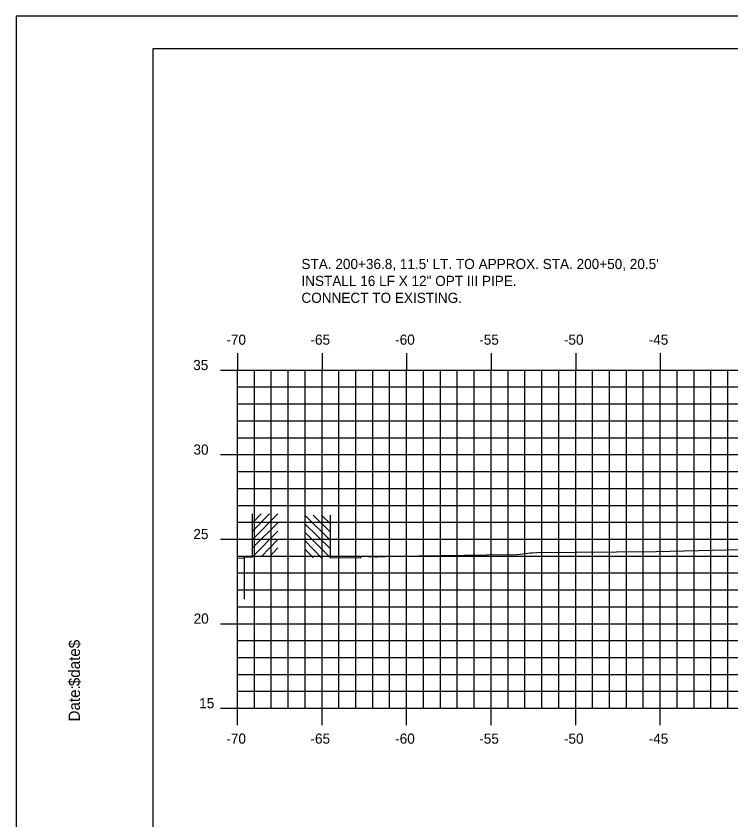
# Model space of a CAD drawing. Extents: x 1023237 to 1023407, y 394697 to 394807.
# Drawn here: x 1023236.57 to 1023278.84, y 394759 to 394806.55 of the extents above; entities that cross this region are included whole.
import ezdxf

# ---------------------------------------------------------------- set-up
doc = ezdxf.new("R2010")
doc.units = 0
for name, color, linetype in [('BORDER', 7, 'Continuous'), ('D_Drainage_Text', 7, 'Continuous'), ('H_V ANNOTATION', 7, 'Continuous'), ('MAJOR', 7, 'Continuous'), ('MINOR', 7, 'Continuous'), ('PLOT BOUNDARY', 7, 'Continuous'), ('S_Buildings_SillElevation', 7, 'Continuous'), ('S_Roadway_Centerline', 7, 'Continuous'), ('S_Roadway_Edge_Pavement', 7, 'Continuous')]:
    doc.layers.add(name, color=color, linetype=linetype)

msp = doc.modelspace()

# ---------------------------------------------------------------- linework, layer by layer
at = {"layer": 'BORDER'}
for p, q in [((1023404.664, 394804.607), (1023244.664, 394804.607)), ((1023244.664, 394804.607), (1023244.664, 394699.607))]:
    msp.add_line(p, q, dxfattribs=at)
at = {"layer": 'MAJOR'}
for p, q in [((1023249.663, 394786.609), (1023249.663, 394785.607)), ((1023254.663, 394786.609), (1023254.663, 394785.607)), ((1023259.663, 394786.609), (1023259.663, 394785.607)), ((1023264.663, 394786.609), (1023264.663, 394785.607)), ((1023269.663, 394786.609), (1023269.663, 394785.607)), ((1023274.663, 394786.609), (1023274.663, 394785.607)), ((1023248.661, 394785.607), (1023249.663, 394785.607)), ((1023249.663, 394785.607), (1023389.663, 394785.607)), ((1023249.663, 394765.607), (1023249.663, 394785.607)), ((1023254.663, 394765.607), (1023254.663, 394785.607)), ((1023259.663, 394765.607), (1023259.663, 394785.607)), ((1023264.663, 394765.607), (1023264.663, 394785.607)), ((1023269.663, 394765.607), (1023269.663, 394785.607)), ((1023274.663, 394765.607), (1023274.663, 394785.607)), ((1023248.661, 394780.607), (1023249.663, 394780.607)), ((1023249.663, 394780.607), (1023389.663, 394780.607)), ((1023248.661, 394775.607), (1023249.663, 394775.607)), ((1023249.663, 394775.607), (1023389.663, 394775.607)), ((1023248.661, 394770.607), (1023249.663, 394770.607)), ((1023249.663, 394770.607), (1023389.663, 394770.607)), ((1023248.661, 394765.607), (1023249.663, 394765.607)), ((1023249.663, 394765.607), (1023389.663, 394765.607)), ((1023249.663, 394764.605), (1023249.663, 394765.607)), ((1023254.663, 394764.605), (1023254.663, 394765.607)), ((1023259.663, 394764.605), (1023259.663, 394765.607)), ((1023264.663, 394764.605), (1023264.663, 394765.607)), ((1023269.663, 394764.605), (1023269.663, 394765.607)), ((1023274.663, 394764.605), (1023274.663, 394765.607))]:
    msp.add_line(p, q, dxfattribs=at)
at = {"layer": 'MINOR'}
for p, q in [((1023250.663, 394765.607), (1023250.663, 394785.607)), ((1023251.663, 394765.607), (1023251.663, 394785.607)), ((1023252.663, 394765.607), (1023252.663, 394785.607)), ((1023253.663, 394765.607), (1023253.663, 394785.607)), ((1023255.663, 394765.607), (1023255.663, 394785.607)), ((1023256.663, 394765.607), (1023256.663, 394785.607)), ((1023257.663, 394765.607), (1023257.663, 394785.607)), ((1023258.663, 394765.607), (1023258.663, 394785.607)), ((1023260.663, 394765.607), (1023260.663, 394785.607)), ((1023261.663, 394765.607), (1023261.663, 394785.607)), ((1023262.663, 394765.607), (1023262.663, 394785.607)), ((1023263.663, 394765.607), (1023263.663, 394785.607)), ((1023265.663, 394765.607), (1023265.663, 394785.607)), ((1023266.663, 394765.607), (1023266.663, 394785.607)), ((1023267.663, 394765.607), (1023267.663, 394785.607)), ((1023268.663, 394765.607), (1023268.663, 394785.607)), ((1023270.663, 394765.607), (1023270.663, 394785.607)), ((1023271.663, 394765.607), (1023271.663, 394785.607)), ((1023272.663, 394765.607), (1023272.663, 394785.607)), ((1023273.663, 394765.607), (1023273.663, 394785.607)), ((1023275.663, 394765.607), (1023275.663, 394785.607)), ((1023276.663, 394765.607), (1023276.663, 394785.607)), ((1023277.663, 394765.607), (1023277.663, 394785.607)), ((1023278.663, 394765.607), (1023278.663, 394785.607)), ((1023249.663, 394784.607), (1023389.663, 394784.607)), ((1023249.663, 394784.607), (1023250.665, 394784.607)), ((1023249.663, 394783.607), (1023389.663, 394783.607)), ((1023249.663, 394783.607), (1023250.665, 394783.607)), ((1023249.663, 394782.607), (1023389.663, 394782.607)), ((1023249.663, 394782.607), (1023250.665, 394782.607)), ((1023249.663, 394781.607), (1023389.663, 394781.607)), ((1023249.663, 394781.607), (1023250.665, 394781.607)), ((1023249.663, 394779.607), (1023389.663, 394779.607)), ((1023249.663, 394779.607), (1023250.665, 394779.607)), ((1023249.663, 394778.607), (1023389.663, 394778.607)), ((1023249.663, 394778.607), (1023250.665, 394778.607)), ((1023249.663, 394777.607), (1023389.663, 394777.607)), ((1023249.663, 394777.607), (1023250.665, 394777.607)), ((1023249.663, 394776.607), (1023389.663, 394776.607)), ((1023249.663, 394776.607), (1023250.665, 394776.607)), ((1023249.663, 394774.607), (1023389.663, 394774.607)), ((1023249.663, 394774.607), (1023250.665, 394774.607)), ((1023249.663, 394773.607), (1023389.663, 394773.607)), ((1023249.663, 394773.607), (1023250.665, 394773.607)), ((1023249.663, 394772.607), (1023389.663, 394772.607)), ((1023249.663, 394772.607), (1023250.665, 394772.607)), ((1023249.663, 394771.607), (1023389.663, 394771.607)), ((1023249.663, 394771.607), (1023250.665, 394771.607)), ((1023249.663, 394769.607), (1023389.663, 394769.607)), ((1023249.663, 394769.607), (1023250.665, 394769.607)), ((1023249.663, 394768.607), (1023389.663, 394768.607)), ((1023249.663, 394768.607), (1023250.665, 394768.607)), ((1023249.663, 394767.607), (1023389.663, 394767.607)), ((1023249.663, 394767.607), (1023250.665, 394767.607)), ((1023249.663, 394766.607), (1023389.663, 394766.607)), ((1023249.663, 394766.607), (1023250.665, 394766.607))]:
    msp.add_line(p, q, dxfattribs=at)
at = {"layer": 'PLOT BOUNDARY'}
msp.add_lwpolyline([(1023236.57, 394696.548), (1023406.57, 394696.548), (1023406.57, 394806.548), (1023236.57, 394806.548)], close=True, dxfattribs=at)
at = {"layer": 'S_Buildings_SillElevation'}
for p, q in [((1023250.547, 394774.568), (1023250.547, 394777.095)), ((1023250.547, 394775.586), (1023252.057, 394777.095)), ((1023250.547, 394776.078), (1023251.565, 394777.095)), ((1023250.547, 394776.57), (1023251.072, 394777.095)), ((1023255.163, 394775.524), (1023253.654, 394777.033)), ((1023255.163, 394776.016), (1023254.146, 394777.033)), ((1023255.163, 394776.508), (1023254.638, 394777.033)), ((1023255.163, 394774.507), (1023255.163, 394777.033)), ((1023250.547, 394775.093), (1023252.057, 394776.57)), ((1023255.163, 394775.032), (1023253.654, 394776.508)), ((1023250.547, 394774.568), (1023252.057, 394776.078)), ((1023255.163, 394774.507), (1023253.654, 394776.016)), ((1023251.072, 394774.568), (1023252.057, 394775.586)), ((1023251.565, 394774.568), (1023252.057, 394775.093)), ((1023254.638, 394774.507), (1023253.654, 394775.524)), ((1023254.146, 394774.507), (1023253.654, 394775.032))]:
    msp.add_line(p, q, dxfattribs=at)
at = {"layer": 'S_Roadway_Centerline'}
for points in [[(1023255.156, 394774.507), (1023256.921, 394774.519), (1023256.968, 394774.52), (1023256.968, 394774.605), (1023256.979, 394774.605), (1023257.835, 394774.556), (1023257.918, 394774.556), (1023258.93, 394774.604), (1023258.947, 394774.605), (1023259.026, 394774.608), (1023265.758, 394774.691), (1023265.867, 394774.687), (1023266.217, 394774.694), (1023266.997, 394774.797), (1023267.062, 394774.805), (1023267.373, 394774.812), (1023274.418, 394774.883), (1023274.775, 394774.887), (1023274.835, 394774.886), (1023275.244, 394774.892), (1023281.097, 394775.028)], [(1023249.663, 394774.487), (1023250.049, 394774.495), (1023250.05, 394774.561), (1023250.548, 394774.568)]]:
    msp.add_lwpolyline(points, dxfattribs=at)
at = {"layer": 'S_Roadway_Edge_Pavement'}
msp.add_line((1023250.05, 394774.561), (1023250.05, 394772.061), dxfattribs=at)

# ---------------------------------------------------------------- texts
at = {"layer": 'BORDER'}
for s, p in [('$date$', (1023240.348, 394766.912)), ('Date:', (1023240.348, 394764.824))]:
    msp.add_text(s, height=0.6696, rotation=90, dxfattribs=at).set_placement(p)
at = {"layer": 'D_Drainage_Text'}
for s, p in [("STA. 200+36.8, 11.5' LT. TO APPROX. STA. 200+50, 20.5' ", (1023253.445, 394791.583)), ('INSTALL 16 LF X 12" OPT III PIPE.', (1023253.445, 394790.583)), ('CONNECT TO EXISTING.', (1023253.445, 394789.583))]:
    msp.add_text(s, height=0.6, dxfattribs=at).set_placement(p)
at = {"layer": 'H_V ANNOTATION'}
for s, p in [('-70', (1023249.005, 394787.107)), ('-65', (1023253.981, 394787.107)), ('-60', (1023258.989, 394787.107)), ('-55', (1023263.96, 394787.107)), ('-50', (1023268.968, 394787.107)), ('-45', (1023273.981, 394787.107)), ('35', (1023247.045, 394785.607)), ('30', (1023247.061, 394780.607)), ('25', (1023247.055, 394775.607)), ('20', (1023247.071, 394770.607)), ('15', (1023247.398, 394765.607)), ('-70', (1023249.005, 394763.507)), ('-65', (1023253.981, 394763.507)), ('-60', (1023258.989, 394763.507)), ('-55', (1023263.96, 394763.507)), ('-50', (1023268.968, 394763.507)), ('-45', (1023273.981, 394763.507))]:
    msp.add_text(s, height=0.6, dxfattribs=at).set_placement(p)

doc.saveas('drawing.dxf')
